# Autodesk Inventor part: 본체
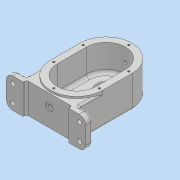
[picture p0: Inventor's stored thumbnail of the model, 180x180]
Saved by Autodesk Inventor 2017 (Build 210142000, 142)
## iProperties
Part Number: 본체
Material: 일반
Document SubType Name: Modeling
Designer: MRC
Density: 1 g/cm^3
Appearance: 기본값
Author: MRC
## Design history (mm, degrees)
sketch "스케치4"
  geometry: L1 (-40, 85)-(40, 85); L2 (40, 85)-(40, -47); L3 (40, -47)-(-40, -47); L4 (-40, -47)-(-40, 85); 1 further point
  constraints: 8 end point, 2 parallel, 1 horizontal, 1 perpendicular
  dimensions: "d7" = 80 distance of L1.start L1.end; "d8" = 132 distance of L1.end L2.end; "d9" = 47 vertical distance of L3.end point (0, 0); "d13" = 40 horizontal distance of point (0, 0) L1.start
extrude "돌출1" new body sketch "스케치4" distance "d10" = 49; taper "d11" = 0 deg
sketch "스케치5"
  geometry: L1 (-40, 45)-(-40, 0); L2 (40, 45)-(40, 0); L3 (40, 85)-(-40, 85) reference; L4 (-40, 85)-(40, 85); L5 (40, 85)-(40, -47); L6 (-40, -47)-(40, -47) reference; L7 (40, -47)-(-40, -47); L8 (-40, -47)-(-40, 85); A1 r 40 centre (0, 0) between (-40, 0) and (40, 0); A2 r 40 centre (0, 45) between (40, 45) and (-40, 45); 1 further point
  constraints: 12 end point, 4 point on circle, 2 centre point, 2 perpendicular, 1 coincident, 1 collinear, 1 horizontal
  dimensions: "d12" = 80 diameter of A1; "d14" = 80 diameter of A2; "d15" = 45 distance of point (0, 0) A2.centre
extrude "돌출2" cut sketch "스케치5" stored distance "d16" = 49; taper "d17" = 0 deg
sketch "스케치6"
  geometry: L1 (-40, 45)-(-40, 0) reference; L2 (-30, 0)-(-30, 45); L3 (30, 0)-(30, 45); A1 r 40 centre (0, 45) between (40, 45) and (-40, 45) reference; A2 r 40 centre (0, 0) between (-40, 0) and (40, 0) reference; A3 r 30 centre (0, 0) between (-30, 0) and (30, 0); A4 r 30 centre (0, 45) between (30, 45) and (-30, 45)
  constraints: 4 end point, 4 point on circle, 2 centre point, 2 coincident, 1 parallel, 1 tangent
  dimensions: "d18" = 60 diameter of A3; "d19" = 60 diameter of A4
extrude "돌출3" cut sketch "스케치6" distance "d20" = 41; taper "d21" = 0 deg
sketch "스케치8"
  geometry: L1 (-40, 0)-(-40, -37); L2 (-40, -37)-(-61, -37); L3 (-61, -37)-(-61, -47); L4 (-61, -47)-(-35, -47); L5 (-35, -47)-(-35, -42); L6 (-35, -42)-(35, -42); L7 (35, -42)-(35, -47); L8 (35, -47)-(61, -47); L9 (61, -47)-(61, -37); L10 (61, -37)-(40, -37); L11 (40, -37)-(40, 0); A1 r 40 centre (0, 45) between (40, 45) and (-40, 45) reference; A2 r 40 centre (0, 0) between (-40, 0) and (40, 0) reference
  constraints: 22 end point, 8 perpendicular, 4 point on line, 2 tangent, 1 vertical
  dimensions: "d25" = 10 distance of L2.end L3.end; "d26" = 70 distance between parallel lines of L7 L5; "d27" = 122 distance between parallel lines of L9 L3; "d28" = 61 distance from line of A1.centre L3; "d29" = 35 distance from line of A2.centre L5; "d30" = 47 distance from line of L8 A2.centre; "d31" = 5 distance between parallel lines of L8 L6
extrude "돌출4" join sketch "스케치8" distance "d32" = 46; taper "d33" = 0 deg
sketch "스케치9"
  geometry: L1 (0, 45)-(0, 0); L2 (-26, 45)-(-26, 0); L3 (26, 0)-(26, 45); A1 r 40 centre (0, 45) between (40, 45) and (-40, 45) reference; A2 r 26 centre (0, 45) between (26, 45) and (-26, 45); A3 r 26 centre (0, 0) between (-26, 0) and (26, 0); 2 further points
  constraints: 8 end point, 4 point on circle, 4 tangent, 2 centre point, 1 midpoint, 1 parallel, 1 vertical
  dimensions: "d34" = 26 radius of A2; "d35" = 45 distance of L1.start L1.end
extrude "돌출5" join sketch "스케치9" distance "d36" = 11; taper "d37" = 0 deg
sketch "스케치10"
  geometry: L1 (26, 0)-(26, 45) reference; L2 (-26, 0)-(-26, 45) reference; L3 (-26, 15)-(26, 15); A1 r 26 centre (0, 45) between (26, 45) and (-26, 45) reference
  constraints: 2 end point, 2 point on line, 1 perpendicular
  dimensions: "d38" = 30 distance from line of A1.centre L3
extrude "돌출6" cut sketch "스케치10" distance "d39" = 3; taper "d40" = 0 deg
hole "구멍1" diameter "d43" = 20; stored, may be unused: countersink angle "d47" = 90 deg, drill point angle "d49" = 0 deg; dims "d41" = 10, "d42" = 10, "d44" = 6, "d45" = 28, "d46" = 8, "d48" = 12
hole "구멍2" diameter "d52" = 22; stored, may be unused: countersink angle "d56" = 90 deg, drill point angle "d58" = 0 deg; dims "d50" = 10, "d51" = 10, "d53" = 6, "d54" = 28, "d55" = 8, "d57" = 100
sketch "스케치11"
  geometry: C1 r 11 at (0, 45) reference; C2 r 14 at (0, 45); A1 r 26 centre (0, 45) between (26, 45) and (-26, 45) reference; 1 further point
  constraints: 1 centre point, 1 coincident
  dimensions: "d59" = 28 diameter of C2
extrude "돌출7" cut sketch "스케치11" distance "d60" = 4; taper "d61" = 0 deg
node "작업 평면1"
sketch "스케치12"
  geometry: C1 r 6 at (0, 28); 1 further point
  constraints: 1 centre point
  dimensions: "d63" = 12 diameter of C1; "d64" = 28 distance of point (0, 0) C1.centre
extrude "돌출8" join sketch "스케치12" stored distance "d65" = 4; taper "d66" = 0 deg
fillet "모깎기1" dims "d67" = 10
sketch "스케치14"
  geometry: A1 r 10 centre (-11, 36) between (-11, 46) and (-21, 36) reference; A2 r 10 centre (-11, 10) between (-21, 10) and (-11, 0) reference; A3 r 10 centre (91, 36) between (101, 36) and (91, 46) reference; A4 r 10 centre (91, 10) between (91, 0) and (101, 10) reference; 5 further points
  constraints: 4 coincident
hole "구멍3" sketch "스케치14" at (-11, 36), (-11, 10), (91, 36), (91, 10) diameter "d68" = 6.6; stored, may be unused: countersink angle "d72" = 90 deg, drill point angle "d74" = 0 deg; dims "d69" = 6, "d70" = 11, "d71" = 2, "d73" = 100
sketch "스케치15"
  geometry: C1 r 6 at (0, 0) reference; 1 further point
hole "구멍4" sketch "스케치15" at (0, 0) diameter "d75" = 4.917; stored, may be unused: countersink angle "d79" = 90 deg, drill point angle "d81" = 0 deg; dims "d76" = 12, "d77" = 11, "d78" = 2, "d80" = 17.1
sketch "스케치16"
  geometry: L1 (75, 49)-(-5, 49) reference; C1 r 6 at (35, 28) reference; 2 further points
  constraints: 1 coincident
hole "구멍5" sketch "스케치16" at (35, 28) diameter "d82" = 4.917; stored, may be unused: countersink angle "d86" = 90 deg, drill point angle "d88" = 0 deg; dims "d83" = 30, "d84" = 12, "d85" = 1, "d87" = 30
sketch "스케치17" dims "d89" = 40
  geometry: A1 r 26 centre (0, 45) between (26, 45) and (-26, 45) reference; 3 further points
  constraints: 1 coincident, 1 vertical alignment, 2 other
hole "구멍6" sketch "스케치17" at (0, 65) diameter "d90" = 3.242; stored, may be unused: countersink angle "d94" = 90 deg, drill point angle "d96" = 118 deg; dims "d91" = 8, "d92" = 11, "d93" = 2, "d95" = 10
sketch "스케치18"
  geometry: L1 (-51.377, 45)-(64.279, 45); A1 r 40 centre (0, 45) between (40, 45) and (-40, 45) reference; A2 r 40 centre (0, 0) between (-40, 0) and (40, 0) reference; A3 r 35 centre (0, 45) between (0, 80) and (-35, 45); A4 r 35 centre (0, 0) between (0, -35) and (-35, 0); 2 further points
  constraints: 6 point on circle, 2 centre point, 2 coincident, 2 end point, 1 horizontal, 1 point on line
  dimensions: "d100" = 70 diameter of A3
hole "구멍7" sketch "스케치18" at (0, 80), (-35, 45), (35, 45), (0, -35), (-35, 0), (35, 0) diameter "d101" = 3.242; stored, may be unused: countersink angle "d105" = 90 deg, drill point angle "d107" = 118 deg; dims "d102" = 8, "d103" = 11, "d104" = 2, "d106" = 10
sketch "스케치19"
  geometry: 3 further points
  constraints: 1 other
  dimensions: "d108" = 35 horizontal distance of point (-35, -42) point (0, -35); "d109" = 12 vertical distance of point (35, -47) point (0, -35)
feature "엠보싱1" sketch "스케치19" dims "d7" = 80, "d8" = 132, "d9" = 47, "d13" = 40, "d110" = 0.7, "d111" = 0
fillet "모깎기2" dims "d112" = 3
fillet "모깎기5" dims "d115" = 3
fillet "모깎기6" dims "d116" = 3
fillet "모깎기7" dims "d117" = 5
fillet "모깎기8" dims "d118" = 3
chamfer "모따기1" distance "d119" = 1; stored, may be unused: second distance "d120" = 2, angle "d121" = 45 deg
fillet "모깎기9" dims "d122" = 0.3
fillet "모깎기10" dims "d123" = 3
node "솔리드1"
pattern_circular "원형 패턴1" dims angle "d98" = 360 deg
other parameters: "d62" = 88
